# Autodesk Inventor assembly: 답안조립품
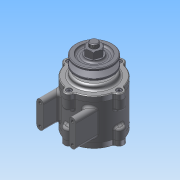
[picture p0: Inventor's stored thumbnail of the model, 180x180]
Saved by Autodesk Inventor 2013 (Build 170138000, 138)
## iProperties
Created: 2015-03
Part Number: 답안조립품
Document SubType Name: Assembly
Designer: ST4
Author: ST4
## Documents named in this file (11)
- C:\Users\ST4\Desktop\450305V1025\답안조립품.iam
- C:\Users\ST4\Desktop\450305V1025\1-본체.ipt
- C:\Users\ST4\Desktop\450305V1025\커버.ipt
- C:\Users\ST4\Desktop\450305V1025\커버2.ipt
- C:\Users\ST4\Desktop\450305V1025\오일실.ipt
- C:\Users\ST4\Desktop\450305V1025\베어링 6204.ipt
- C:\Users\ST4\Desktop\450305V1025\축.ipt
- C:\Users\ST4\Desktop\450305V1025\키(4 x 4 x 12).ipt
- C:\Users\ST4\Desktop\450305V1025\V벨트풀리.ipt
- C:\Users\ST4\Desktop\450305V1025\너트 M12x1.25.ipt
- C:\Users\ST4\Desktop\450305V1025\M 4 x 12.ipt
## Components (15 placed, 7 different names)
1. 1-본체:1
2. KS B 2804 D D - 20 32 8:1
3. KS B 2023 6204 - 20 x 47 x 14:1
4. KS B 2023 6204 - 20 x 47 x 14:2
5. KS B 1311 (I) 4 x 4 x 12:1
6. 그루브 풀리1:1
7. KS B 1012 클래스 1 일반 - 미터 M12x1.25:1
8. KS B 1003 - 미터 M 4 x 12:1
9. KS B 1003 - 미터 M 4 x 12:2
10. KS B 1003 - 미터 M 4 x 12:3
11. KS B 1003 - 미터 M 4 x 12:4
12. KS B 1003 - 미터 M 4 x 12:5
13. KS B 1003 - 미터 M 4 x 12:6
14. KS B 1003 - 미터 M 4 x 12:7
15. KS B 1003 - 미터 M 4 x 12:8
